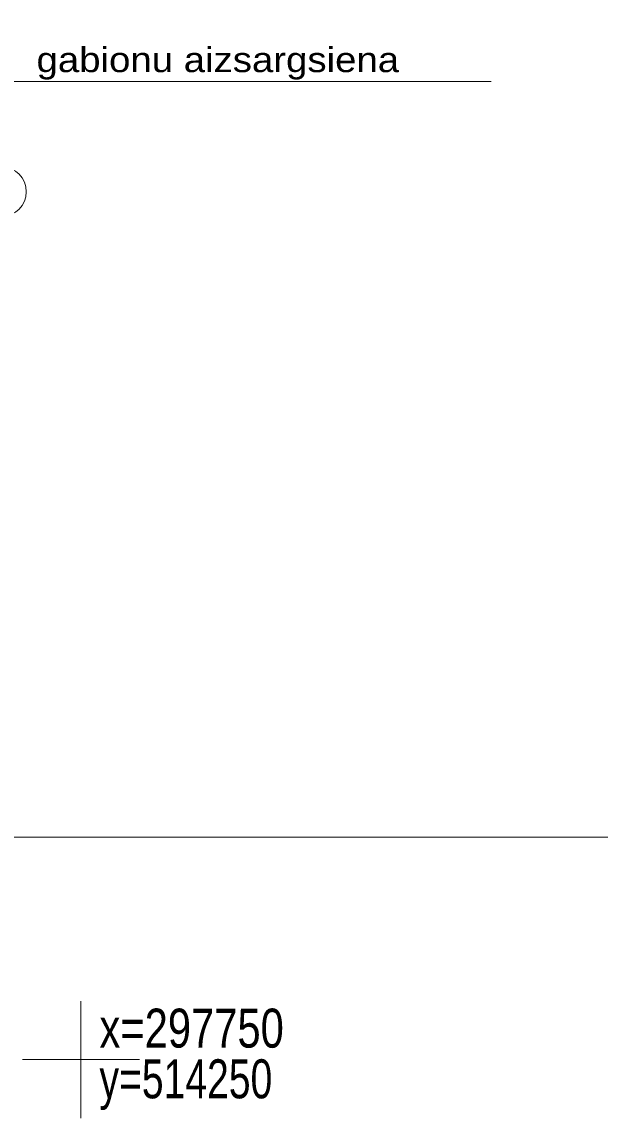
# Model space of a CAD drawing. Extents: x -1320 to -1174, y 762 to 862.
# Drawn here: x -1247.02 to -1232.19, y 769.09 to 797.2 of the extents above; entities that cross this region are included whole.
import ezdxf
from ezdxf.enums import TextEntityAlignment as Align

# ---------------------------------------------------------------- set-up
doc = ezdxf.new("R2010")
doc.units = 0
doc.header["$LTSCALE"] = 0.2
for name, color, linetype, lineweight in [('1', 7, 'Continuous', 13), ('19', 7, 'Continuous', 25), ('22', 7, 'Continuous', 13), ('25', 7, 'Continuous', 13), ('62', 7, 'Continuous', 13), ('63', 7, 'Continuous', 13)]:
    doc.layers.add(name, color=color, linetype=linetype, lineweight=lineweight)
doc.layers.add('26', color=7, linetype='Continuous')

msp = doc.modelspace()

# ---------------------------------------------------------------- linework, layer by layer
at = {"layer": '1'}
msp.add_circle((-1247.5401, 792.844), 0.635, dxfattribs=at)
msp.add_spline([(-1235.8, 825.801), (-1237.913, 825.174), (-1239.203, 823.346), (-1241.709, 821.268), (-1246.557, 815.58), (-1256.526, 805.053), (-1260.592, 799.147), (-1261.416, 795.29), (-1262.742, 791.444), (-1262.206, 785.139)], degree=3, dxfattribs=at)
at = {"layer": '19', "lineweight": 13}
msp.add_spline([(-1253.457, 785.393), (-1253.726, 794.104), (-1251.637, 801.373), (-1250.122, 804.26), (-1247.608, 807.348), (-1239.437, 815.545), (-1236.508, 819.221), (-1228.799, 821.851), (-1223.357, 826.161), (-1220.079, 827.95)], degree=3, dxfattribs=at)
at = {"layer": '22'}
msp.add_lwpolyline([(-1182.029, 847.654), (-1319.805, 847.654), (-1319.805, 776.291), (-1182.029, 776.291)], close=True, dxfattribs=at)
at = {"layer": '25'}
for points in [[(-1245.505, 772.086), (-1245.505, 770.586), (-1245.505, 769.086)], [(-1245.505, 772.086), (-1245.505, 770.586), (-1245.505, 769.086)], [(-1245.505, 772.086), (-1245.505, 770.586), (-1245.505, 769.086)], [(-1247.005, 770.586), (-1245.505, 770.586), (-1244.005, 770.586)], [(-1247.005, 770.586), (-1245.505, 770.586), (-1244.005, 770.586)], [(-1247.005, 770.586), (-1245.505, 770.586), (-1244.005, 770.586)]]:
    msp.add_lwpolyline(points, dxfattribs=at)
at = {"layer": '62'}
msp.add_spline([(-1254.434, 786.21), (-1255.853, 794.247), (-1253.373, 799.783), (-1252.196, 801.907), (-1252.103, 801.965), (-1250.675, 804.058), (-1247.791, 807.511), (-1245.419, 810.213), (-1244.186, 811.494), (-1242.939, 812.764), (-1240.149, 815.75), (-1236.129, 820.169), (-1233.075, 822.242), (-1235.394, 825.816)], degree=3, dxfattribs=at)
at = {"layer": '63'}
msp.add_lwpolyline([(-1254.837, 789.362), (-1247.335, 795.673), (-1234.983, 795.673)], dxfattribs=at)

# ---------------------------------------------------------------- texts
at = {"layer": '26'}
for s, width, p in [('x=297750', 0.8, (-1245.028, 770.893)), ('y=514250', 0.75, (-1245.028, 769.593))]:
    msp.add_text(s, height=1, dxfattribs=dict(at, width=width)).set_placement(p)
at = {"layer": '63', "width": 1.15}
msp.add_text('gabionu aizsargsiena', height=0.64, dxfattribs=at).set_placement((-1241.9915, 795.91), align=Align.CENTER)

doc.saveas('drawing.dxf')
